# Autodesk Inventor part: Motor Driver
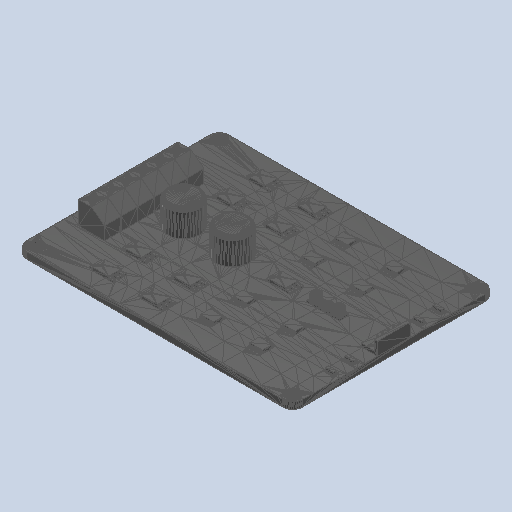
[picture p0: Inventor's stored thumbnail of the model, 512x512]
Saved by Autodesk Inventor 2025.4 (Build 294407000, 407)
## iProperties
Created: 2026-09
Part Number: Motor Driver
Material: Genérico
Document SubType Name: Modeling
Designer: usuario
Density: 1 g/cm^3
Appearance: Valor por defecto
Author: usuario
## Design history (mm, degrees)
node "Motor Driver"
  node "MeshFeature1"
